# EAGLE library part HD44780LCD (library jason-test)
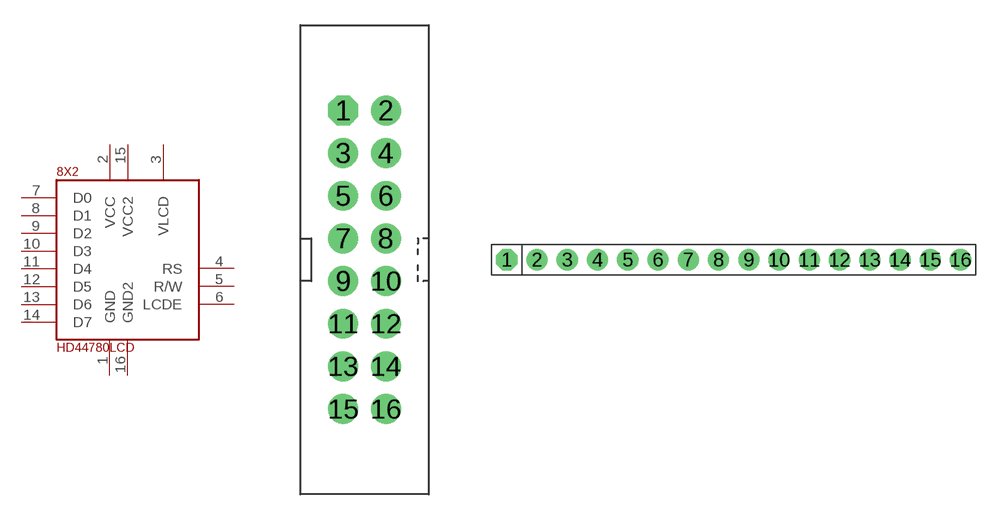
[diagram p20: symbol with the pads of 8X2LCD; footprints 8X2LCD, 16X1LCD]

Designator prefix 8X2

## HD44780LCD8X2  [8X2LCD]
1  GND  pwr
2  VCC  pwr
3  VLCD  pwr
4  RS  in
5  R/W  in
6  LCDE  in
7  D0
8  D1
9  D2
10  D3
11  D4
12  D5
13  D6
14  D7
15  VCC2  pwr
16  GND2  pwr

## HD44780LCD16X1  [16X1LCD]
Pads as for 8X2LCD

## HD44780LCD16X1FPC  [16X1LCD_FPC]
Pads as for 8X2LCD

## Footprint 8X2LCD (pad centres in mm)
drill 1 pad 1.778 octagon: 1 -1.27,8.89
drill 1 pad 1.778 round: 2 1.27,8.89; 3 -1.27,6.35; 4 1.27,6.35; 5 -1.27,3.81; 6 1.27,3.81; 7 -1.27,1.27; 8 1.27,1.27; 9 -1.27,-1.27; 10 1.27,-1.27; 11 -1.27,-3.81; 12 1.27,-3.81; 13 -1.27,-6.35; 14 1.27,-6.35; 15 -1.27,-8.89; 16 1.27,-8.89

## Footprint 16X1LCD (pad centres in mm)
drill 1 pad 1.778 octagon: 1 -19.05,0
drill 1 pad 1.778 round: 2 -16.51,0; 3 -13.97,0; 4 -11.43,0; 5 -8.89,0; 6 -6.35,0; 7 -3.81,0; 8 -1.27,0; 9 1.27,0; 10 3.81,0; 11 6.35,0; 12 8.89,0; 13 11.43,0; 14 13.97,0; 15 16.51,0; 16 19.05,0

## Footprint 16X1LCD_FPC (pad centres in mm)
smd 0.61 x 2: 1 -7.5,1; 2 -6.5,1; 3 -5.5,1; 4 -4.5,1; 5 -3.5,1; 6 -2.5,1; 7 -1.5,1; 8 -0.5,1; 9 0.5,1; 10 1.5,1; 11 2.5,1; 12 3.5,1; 13 4.5,1; 14 5.5,1; 15 6.5,1; 16 7.5,1
smd 2.68 x 3.6: P$17 -11.5,-2; P$18 11.5,-2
